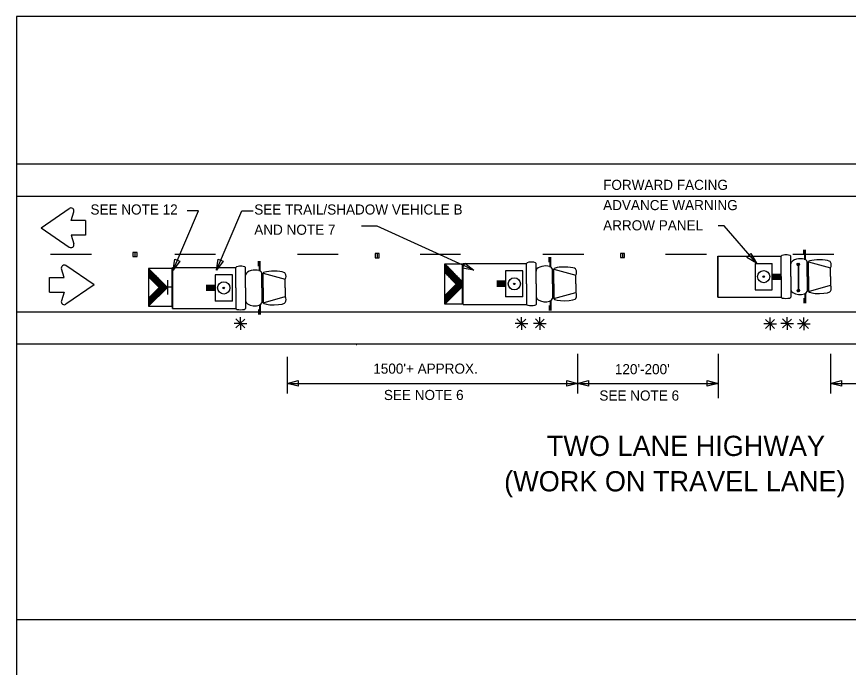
# Model space of a CAD drawing. Extents: x 1806907 to 1812607, y 675071 to 676228.
# Drawn here: x 1810956.7 to 1811449.9, y 675735.3 to 676121.2 of the extents above; entities that cross this region are included whole.
import ezdxf

# ---------------------------------------------------------------- set-up
doc = ezdxf.new("R2010")
doc.units = 0
for name, color, linetype in [('DSN_DRFT_Named-Boundary', 7, 'Continuous'), ('Level 1', 7, 'Continuous'), ('Working Level 1', 7, 'Continuous')]:
    doc.layers.add(name, color=color, linetype=linetype)

msp = doc.modelspace()

# ---------------------------------------------------------------- linework, layer by layer
at = {"layer": 'DSN_DRFT_Named-Boundary'}
msp.add_lwpolyline([(1810956.68, 675071.2), (1812606.68, 675071.2), (1812606.68, 676121.2), (1810956.68, 676121.2)], close=True, dxfattribs=at)
at = {"layer": 'Level 1'}
for points in [[(1811049.43, 675970.8), (1811064.48, 676006.06), (1811057.79, 676006.06)], [(1811075.16, 675970.8), (1811090.2, 676006.06), (1811096.89, 676006.06)], [(1811227.71, 675970.8), (1811170.45, 675996.86), (1811161.11, 675996.86)]]:
    msp.add_lwpolyline(points, dxfattribs=at)
at = {"layer": 'Working Level 1'}
for p, q in [((1810956.95, 676033.93), (1811756.7, 676033.93)), ((1810956.95, 676014.8), (1811756.7, 676014.8)), ((1810971.22, 675995.97), (1810987.89, 676007.41)), ((1810988.94, 676000.34), (1810990.57, 676005.41)), ((1810971.22, 675995.97), (1810987.89, 675984.54)), ((1810997.61, 676000.34), (1810988.94, 676000.34)), ((1810997.61, 676000.34), (1810997.61, 675991.61)), ((1810997.61, 675991.61), (1810988.94, 675991.61)), ((1810988.94, 675991.61), (1810990.57, 675986.53)), ((1811025.64, 675981.41), (1811025.63, 675978.98)), ((1811028.06, 675981.41), (1811025.64, 675981.41)), ((1811026.86, 675981.41), (1811026.85, 675978.98)), ((1811028.06, 675978.98), (1811028.06, 675981.41)), ((1811423.53, 675979.86), (1811423.53, 675982.83)), ((1811424, 675977), (1811424, 675982.83)), ((1811424.4, 675977), (1811424.4, 675982.83)), ((1811025.63, 675978.98), (1811028.06, 675978.98)), ((1811100.2, 675973.15), (1811100.2, 675976.12)), ((1811100.67, 675970.3), (1811100.67, 675976.12)), ((1811101.07, 675970.3), (1811101.07, 675976.12)), ((1811169.32, 675980.67), (1811169.31, 675978.24)), ((1811169.31, 675978.24), (1811171.74, 675978.24)), ((1811171.74, 675980.67), (1811169.32, 675980.67)), ((1811170.53, 675980.67), (1811170.53, 675978.24)), ((1811171.74, 675978.24), (1811171.74, 675980.67)), ((1811272.5, 675975.56), (1811272.5, 675978.53)), ((1811272.97, 675972.7), (1811272.97, 675978.53)), ((1811273.37, 675972.7), (1811273.37, 675978.53)), ((1811314.76, 675980.81), (1811314.75, 675978.38)), ((1811314.75, 675978.38), (1811317.18, 675978.38)), ((1811317.18, 675980.81), (1811314.76, 675980.81)), ((1811315.97, 675980.81), (1811315.97, 675978.38)), ((1811317.18, 675978.38), (1811317.18, 675980.81)), ((1811372.48, 675979.14), (1811372.48, 675954.88)), ((1811372.48, 675979.13), (1811410.02, 675979.13)), ((1811372.48, 675954.88), (1811372.48, 675979.13)), ((1811410.02, 675967.01), (1811410.02, 675979.13)), ((1811415.78, 675967.01), (1811415.78, 675979.13)), ((1810984.89, 675966.48), (1810983.26, 675971.55)), ((1811002.61, 675962.11), (1810985.94, 675973.55)), ((1811034.88, 675971.79), (1811046.07, 675960.62)), ((1811049.15, 675972.43), (1811086.69, 675972.43)), ((1811049.15, 675948.17), (1811049.15, 675972.43)), ((1811049.15, 675972.43), (1811049.15, 675948.18)), ((1811086.69, 675960.3), (1811086.69, 675972.43)), ((1811092.44, 675960.3), (1811092.44, 675972.43)), ((1811210.58, 675974.55), (1811220.94, 675964.2)), ((1811221.45, 675974.83), (1811258.99, 675974.83)), ((1811221.45, 675950.58), (1811221.45, 675974.83)), ((1811258.99, 675962.71), (1811258.99, 675974.83)), ((1811264.75, 675962.71), (1811264.75, 675974.83)), ((1811274.38, 675962.71), (1811274.38, 675971.44)), ((1811275.18, 675971.44), (1811288.31, 675967.85)), ((1811275.18, 675962.71), (1811275.18, 675971.44)), ((1811394.53, 675974.77), (1811404.79, 675974.77)), ((1811394.53, 675974.77), (1811394.53, 675959.25)), ((1811404.79, 675959.25), (1811404.79, 675974.77)), ((1811419.44, 675974.38), (1811419.44, 675974.38)), ((1811420.06, 675974.03), (1811420.06, 675958.98)), ((1811420.1, 675974.03), (1811420.1, 675958.98)), ((1811420.15, 675974.03), (1811420.15, 675958.98)), ((1811420.23, 675974.03), (1811420.23, 675958.98)), ((1811420.32, 675974.89), (1811420.32, 675974.89)), ((1811420.34, 675974.03), (1811420.34, 675958.98)), ((1811425.41, 675967.01), (1811425.41, 675975.74)), ((1811426.21, 675975.74), (1811439.34, 675972.15)), ((1811426.21, 675967.01), (1811426.21, 675975.74)), ((1811439.34, 675967.01), (1811439.34, 675972.15)), ((1810976.22, 675957.75), (1810976.22, 675966.48)), ((1810976.22, 675966.48), (1810984.89, 675966.48)), ((1811034.88, 675966.94), (1811041.29, 675960.55)), ((1811084.62, 675968.06), (1811074.36, 675968.06)), ((1811074.36, 675968.06), (1811074.36, 675952.54)), ((1811084.62, 675952.54), (1811084.62, 675968.06)), ((1811102.08, 675960.3), (1811102.08, 675969.04)), ((1811102.88, 675969.04), (1811116.01, 675965.45)), ((1811102.88, 675960.3), (1811102.88, 675969.04)), ((1811210.58, 675969.37), (1811217.41, 675962.57)), ((1811256.93, 675970.47), (1811246.66, 675970.47)), ((1811246.66, 675970.47), (1811246.66, 675954.94)), ((1811256.93, 675954.94), (1811256.93, 675970.47)), ((1811288.31, 675962.71), (1811288.31, 675967.85)), ((1811404.79, 675968.56), (1811410.02, 675968.56)), ((1811404.79, 675967.78), (1811410.02, 675967.78)), ((1811404.79, 675967.01), (1811410.02, 675967.01)), ((1811404.79, 675966.23), (1811410.02, 675966.23)), ((1811410.02, 675967.01), (1811410.02, 675954.88)), ((1811415.78, 675967.01), (1811415.78, 675954.88)), ((1811425.41, 675967.01), (1811425.41, 675958.27)), ((1811426.21, 675967.01), (1811426.21, 675958.27)), ((1811439.34, 675967.01), (1811439.34, 675961.86)), ((1811002.61, 675962.11), (1810985.94, 675950.68)), ((1811046.44, 675956.41), (1811046.44, 675964.82)), ((1811074.36, 675961.85), (1811069.13, 675961.85)), ((1811116.01, 675960.3), (1811116.01, 675965.45)), ((1811210.58, 675955.75), (1811217.41, 675962.57)), ((1811246.66, 675964.26), (1811241.44, 675964.26)), ((1811246.66, 675963.48), (1811241.44, 675963.48)), ((1811246.66, 675962.71), (1811241.44, 675962.71)), ((1811246.66, 675961.93), (1811241.44, 675961.93)), ((1811258.99, 675962.71), (1811258.99, 675950.58)), ((1811264.75, 675962.71), (1811264.75, 675950.58)), ((1811274.38, 675962.71), (1811274.38, 675953.97)), ((1811275.18, 675962.71), (1811275.18, 675953.97)), ((1811288.31, 675962.71), (1811288.31, 675957.56)), ((1811404.79, 675965.46), (1811410.02, 675965.46)), ((1811426.21, 675958.27), (1811439.34, 675961.86)), ((1810976.22, 675957.75), (1810984.89, 675957.75)), ((1810984.89, 675957.75), (1810983.26, 675952.68)), ((1811034.88, 675954.16), (1811041.29, 675960.55)), ((1811034.95, 675949.49), (1811046.07, 675960.62)), ((1811048.78, 675960.81), (1811046.37, 675960.81)), ((1811074.36, 675961.08), (1811069.13, 675961.08)), ((1811074.36, 675960.3), (1811069.13, 675960.3)), ((1811074.36, 675959.52), (1811069.13, 675959.52)), ((1811074.36, 675958.75), (1811069.13, 675958.75)), ((1811086.69, 675960.3), (1811086.69, 675948.18)), ((1811092.44, 675960.3), (1811092.44, 675948.18)), ((1811102.08, 675960.3), (1811102.08, 675951.57)), ((1811102.88, 675960.3), (1811102.88, 675951.57)), ((1811116.01, 675960.3), (1811116.01, 675955.15)), ((1811210.64, 675950.77), (1811220.89, 675961.02)), ((1811246.66, 675961.15), (1811241.44, 675961.15)), ((1811275.18, 675953.97), (1811288.31, 675957.56)), ((1811394.53, 675959.25), (1811404.79, 675959.25)), ((1811419.49, 675958.85), (1811419.49, 675958.85)), ((1811420.36, 675959.36), (1811420.36, 675959.36)), ((1811424, 675957.01), (1811424, 675951.19)), ((1811424.4, 675957.01), (1811424.4, 675951.19)), ((1811084.62, 675952.54), (1811074.36, 675952.54)), ((1811102.88, 675951.57), (1811116.01, 675955.15)), ((1811256.93, 675954.94), (1811246.66, 675954.94)), ((1811272.97, 675952.71), (1811272.97, 675946.88)), ((1811273.37, 675952.71), (1811273.37, 675946.88)), ((1811372.48, 675954.88), (1811410.02, 675954.88)), ((1811423.53, 675954.16), (1811423.53, 675951.19)), ((1811049.15, 675948.18), (1811086.69, 675948.18)), ((1811100.2, 675947.45), (1811100.2, 675944.48)), ((1811100.67, 675950.3), (1811100.67, 675944.48)), ((1811101.07, 675950.3), (1811101.07, 675944.48)), ((1811221.45, 675950.58), (1811258.99, 675950.58)), ((1811272.5, 675949.85), (1811272.5, 675946.88)), ((1810956.95, 675946.11), (1811756.7, 675946.11)), ((1811089.4, 675939.23), (1811086.74, 675941.89)), ((1811089.33, 675939.18), (1811092, 675941.84)), ((1811089.4, 675939.23), (1811089.4, 675943)), ((1811255.99, 675939.23), (1811253.33, 675941.89)), ((1811255.93, 675939.18), (1811258.59, 675941.84)), ((1811255.99, 675939.23), (1811255.99, 675943)), ((1811266.97, 675939.23), (1811264.31, 675941.89)), ((1811266.91, 675939.18), (1811269.57, 675941.84)), ((1811266.97, 675939.23), (1811266.97, 675943)), ((1811403.49, 675938.99), (1811400.83, 675941.65)), ((1811403.43, 675938.94), (1811406.09, 675941.6)), ((1811403.49, 675938.99), (1811403.49, 675942.76)), ((1811413.52, 675939.23), (1811410.86, 675941.89)), ((1811413.45, 675939.18), (1811416.12, 675941.84)), ((1811413.52, 675939.23), (1811413.52, 675943)), ((1811423.54, 675938.99), (1811420.88, 675941.65)), ((1811423.48, 675938.94), (1811426.14, 675941.6)), ((1811423.54, 675938.99), (1811423.54, 675942.76)), ((1811089.4, 675939.23), (1811085.63, 675939.23)), ((1811089.4, 675939.23), (1811086.74, 675936.57)), ((1811089.4, 675939.23), (1811092.06, 675936.57)), ((1811089.4, 675939.23), (1811089.4, 675935.47)), ((1811089.4, 675939.23), (1811093.16, 675939.23)), ((1811255.99, 675939.23), (1811252.23, 675939.23)), ((1811255.99, 675939.23), (1811253.33, 675936.57)), ((1811255.99, 675939.23), (1811258.65, 675936.57)), ((1811255.99, 675939.23), (1811255.99, 675935.47)), ((1811255.99, 675939.23), (1811259.75, 675939.23)), ((1811266.97, 675939.23), (1811263.21, 675939.23)), ((1811266.97, 675939.23), (1811264.31, 675936.57)), ((1811266.97, 675939.23), (1811269.63, 675936.57)), ((1811266.97, 675939.23), (1811266.97, 675935.47)), ((1811266.97, 675939.23), (1811270.73, 675939.23)), ((1811403.49, 675938.99), (1811399.73, 675938.99)), ((1811403.49, 675938.99), (1811400.83, 675936.33)), ((1811403.49, 675938.99), (1811406.15, 675936.33)), ((1811403.49, 675938.99), (1811403.49, 675935.23)), ((1811403.49, 675938.99), (1811407.25, 675938.99)), ((1811413.52, 675939.23), (1811409.75, 675939.23)), ((1811413.52, 675939.23), (1811410.86, 675936.57)), ((1811413.52, 675939.23), (1811416.18, 675936.57)), ((1811413.52, 675939.23), (1811413.52, 675935.47)), ((1811413.52, 675939.23), (1811417.28, 675939.23)), ((1811423.54, 675938.99), (1811419.78, 675938.99)), ((1811423.54, 675938.99), (1811420.88, 675936.33)), ((1811423.54, 675938.99), (1811426.2, 675936.33)), ((1811423.54, 675938.99), (1811423.54, 675935.23)), ((1811423.54, 675938.99), (1811427.3, 675938.99)), ((1810956.95, 675927.23), (1811756.7, 675927.23)), ((1811158.42, 675926.63), (1811157.94, 675926.63)), ((1811117.08, 675919.43), (1811117.08, 675897.64)), ((1811289.35, 675921.17), (1811289.35, 675897.64)), ((1811372.64, 675921.17), (1811372.64, 675894.99)), ((1811439.23, 675921.17), (1811439.23, 675897.64)), ((1811117.08, 675903.7), (1811289.35, 675903.7)), ((1811117.08, 675903.7), (1811122.85, 675903.7)), ((1811289.35, 675903.7), (1811288.19, 675903.7)), ((1811289.35, 675903.7), (1811293.89, 675903.7)), ((1811289.35, 675903.7), (1811372.64, 675903.7)), ((1811372.64, 675903.7), (1811368.13, 675903.7)), ((1811439.23, 675903.7), (1811443.77, 675903.7)), ((1811439.32, 675903.7), (1811522.61, 675903.7)), ((1810956.95, 675763.73), (1811757, 675763.73))]:
    msp.add_line(p, q, dxfattribs=at)
for points in [[(1811395.33, 675974.91), (1811376.24, 675997.09), (1811372.6, 675997.09)], [(1810976.79, 675980.35), (1811001.05, 675980.35)], [(1811050.43, 675980.35), (1811074.69, 675980.35)], [(1811123.19, 675980.35), (1811147.44, 675980.35)], [(1811195.94, 675980.35), (1811219.9, 675980.35)], [(1811268.7, 675980.35), (1811292.95, 675980.35)], [(1811341.45, 675980.35), (1811365.71, 675980.35)], [(1811416.95, 675980.35), (1811441.2, 675980.35)], [(1811034.88, 675971.26), (1811040.79, 675961.05)], [(1811035.38, 675971.3), (1811043.19, 675957.75)], [(1811210.58, 675974), (1811216.87, 675963.1)], [(1811210.58, 675973.06), (1811215.63, 675964.31)], [(1811210.58, 675972.12), (1811214.38, 675965.53)], [(1811210.58, 675971.18), (1811213.14, 675966.76)], [(1811211.11, 675974.03), (1811219.44, 675959.59)], [(1811212.39, 675972.74), (1811219.79, 675959.93)], [(1811213.67, 675971.47), (1811220.13, 675960.27)], [(1811419.42, 675974.12), (1811419.69, 675973.66)], [(1811419.44, 675974.38), (1811419.93, 675973.53)], [(1811419.5, 675974.56), (1811420.12, 675973.5)], [(1811419.59, 675974.7), (1811420.28, 675973.51)], [(1811419.7, 675974.8), (1811420.42, 675973.56)], [(1811419.82, 675974.88), (1811420.55, 675973.62)], [(1811419.97, 675974.92), (1811420.66, 675973.72)], [(1811420.12, 675974.96), (1811420.76, 675973.85)], [(1811420.3, 675974.93), (1811420.83, 675974.01)], [(1811420.51, 675974.85), (1811420.87, 675974.24)], [(1811034.88, 675970.39), (1811039.62, 675962.19)], [(1811034.88, 675969.51), (1811038.45, 675963.33)], [(1811034.88, 675968.63), (1811037.28, 675964.48)], [(1811034.88, 675967.75), (1811036.11, 675965.63)], [(1811034.88, 675966.87), (1811034.95, 675966.77)], [(1811036.58, 675970.09), (1811043.52, 675958.07)], [(1811037.77, 675968.9), (1811043.84, 675958.4)], [(1811038.98, 675967.7), (1811044.16, 675958.71)], [(1811040.17, 675966.5), (1811044.48, 675959.04)], [(1811210.58, 675970.24), (1811211.89, 675967.98)], [(1811210.58, 675969.31), (1811210.64, 675969.2)], [(1811214.95, 675970.19), (1811220.47, 675960.61)], [(1811216.22, 675968.91), (1811220.82, 675960.95)], [(1811217.5, 675967.63), (1811220.9, 675961.75)], [(1811218.78, 675966.36), (1811220.92, 675962.67)], [(1811041.37, 675965.3), (1811044.82, 675959.34)], [(1811042.57, 675964.1), (1811045.15, 675959.65)], [(1811043.77, 675962.91), (1811045.44, 675960.01)], [(1811044.88, 675961.82), (1811045.74, 675960.32)], [(1811216.23, 675961.4), (1811218.07, 675958.22)], [(1811216.58, 675961.74), (1811218.41, 675958.56)], [(1811216.92, 675962.08), (1811218.76, 675958.9)], [(1811217.26, 675962.42), (1811219.1, 675959.24)], [(1811220.06, 675965.09), (1811220.93, 675963.57)], [(1811037.29, 675956.56), (1811039.01, 675953.58)], [(1811037.61, 675956.88), (1811039.33, 675953.9)], [(1811037.93, 675957.2), (1811039.65, 675954.23)], [(1811038.25, 675957.53), (1811039.97, 675954.55)], [(1811038.57, 675957.84), (1811040.29, 675954.87)], [(1811038.9, 675958.17), (1811040.62, 675955.18)], [(1811039.22, 675958.49), (1811040.94, 675955.51)], [(1811039.54, 675958.8), (1811041.26, 675955.83)], [(1811039.86, 675959.13), (1811041.59, 675956.15)], [(1811040.18, 675959.45), (1811041.91, 675956.47)], [(1811040.51, 675959.77), (1811042.23, 675956.79)], [(1811040.82, 675960.1), (1811042.56, 675957.11)], [(1811041.15, 675960.42), (1811042.88, 675957.43)], [(1811211.42, 675956.59), (1811213.25, 675953.43)], [(1811211.77, 675956.94), (1811213.6, 675953.77)], [(1811212.11, 675957.28), (1811213.94, 675954.12)], [(1811212.46, 675957.62), (1811214.29, 675954.45)], [(1811212.8, 675957.96), (1811214.63, 675954.8)], [(1811213.15, 675958.31), (1811214.97, 675955.14)], [(1811213.49, 675958.65), (1811215.32, 675955.48)], [(1811213.83, 675959), (1811215.66, 675955.82)], [(1811214.17, 675959.34), (1811216.01, 675956.16)], [(1811214.51, 675959.68), (1811216.35, 675956.51)], [(1811214.86, 675960.02), (1811216.7, 675956.85)], [(1811215.2, 675960.37), (1811217.04, 675957.19)], [(1811215.55, 675960.71), (1811217.38, 675957.53)], [(1811215.89, 675961.05), (1811217.72, 675957.87)], [(1811419.47, 675958.59), (1811419.73, 675958.13)], [(1811419.49, 675958.85), (1811419.97, 675958)], [(1811419.55, 675959.03), (1811420.16, 675957.97)], [(1811419.64, 675959.17), (1811420.32, 675957.98)], [(1811419.74, 675959.27), (1811420.46, 675958.03)], [(1811419.86, 675959.35), (1811420.59, 675958.09)], [(1811420.01, 675959.39), (1811420.7, 675958.19)], [(1811420.16, 675959.42), (1811420.8, 675958.32)], [(1811420.34, 675959.4), (1811420.87, 675958.48)], [(1811420.56, 675959.32), (1811420.91, 675958.71)], [(1811034.88, 675953.68), (1811036.43, 675951.02)], [(1811034.88, 675952.8), (1811036.1, 675950.7)], [(1811034.88, 675951.92), (1811035.78, 675950.38)], [(1811035.03, 675954.31), (1811036.75, 675951.35)], [(1811035.36, 675954.63), (1811037.07, 675951.66)], [(1811035.68, 675954.95), (1811037.39, 675951.98)], [(1811036, 675955.28), (1811037.72, 675952.3)], [(1811036.32, 675955.59), (1811038.04, 675952.63)], [(1811036.64, 675955.91), (1811038.36, 675952.94)], [(1811036.96, 675956.23), (1811038.68, 675953.26)], [(1811210.58, 675955.25), (1811212.23, 675952.4)], [(1811210.58, 675954.31), (1811211.88, 675952.06)], [(1811210.58, 675953.36), (1811211.54, 675951.72)], [(1811210.58, 675952.43), (1811211.19, 675951.37)], [(1811210.58, 675951.49), (1811210.85, 675951.04)], [(1811210.74, 675955.91), (1811212.56, 675952.75)], [(1811211.09, 675956.25), (1811212.91, 675953.08)], [(1811034.88, 675951.04), (1811035.46, 675950.06)], [(1811034.88, 675950.16), (1811035.13, 675949.74)]]:
    msp.add_lwpolyline(points, dxfattribs=at)
for points in [[(1811053.48, 675976.14), (1811049.43, 675970.8), (1811050.49, 675977.42)], [(1811079.2, 675976.14), (1811075.16, 675970.8), (1811076.21, 675977.42)], [(1811391.95, 675980.69), (1811395.33, 675974.91), (1811389.63, 675978.42)], [(1811034.88, 675971.79), (1811034.88, 675949.48), (1811048.82, 675949.48), (1811048.82, 675971.79)], [(1811220.97, 675950.77), (1811210.58, 675950.77), (1811210.58, 675974.55), (1811220.97, 675974.55)], [(1811222.46, 675974.97), (1811227.71, 675970.8), (1811221.12, 675972.01)], [(1811123.58, 675902.08), (1811117.08, 675903.7), (1811123.58, 675905.33)], [(1811282.85, 675905.33), (1811289.35, 675903.7), (1811282.85, 675902.08)], [(1811295.85, 675902.08), (1811289.35, 675903.7), (1811295.85, 675905.33)], [(1811366.14, 675905.33), (1811372.64, 675903.7), (1811366.14, 675902.08)], [(1811445.73, 675902.08), (1811439.23, 675903.7), (1811445.73, 675905.33)]]:
    msp.add_lwpolyline(points, close=True, dxfattribs=at)
for centre, radius in [((1811420.14, 675974.23), 0.728), ((1811251.8, 675962.71), 3.62), ((1811399.66, 675967.01), 3.62), ((1811399.66, 675967.01), 0.451), ((1811079.49, 675960.3), 3.62), ((1811251.8, 675962.71), 0.451), ((1811079.49, 675960.3), 0.451), ((1811420.18, 675958.69), 0.728)]:
    msp.add_circle(centre, radius, dxfattribs=at)
for centre, radius, start, end in [((1810988.88, 676005.95), 1.77, 342.1824, 124.4455), ((1810988.88, 675985.99), 1.77, 235.5545, 17.8176), ((1810984.95, 675972.09), 1.77, 55.5545, 197.8176), ((1811285.1, 675969.57), 3.64, 331.8801, 28.1199), ((1811436.13, 675973.87), 3.64, 331.8801, 28.1199), ((1811112.8, 675967.16), 3.64, 331.8801, 28.1199), ((1811436.13, 675960.14), 3.64, 331.8801, 28.1199), ((1811285.1, 675955.84), 3.64, 331.8801, 28.1199), ((1810984.95, 675952.14), 1.77, 162.1824, 304.4455), ((1811112.8, 675953.44), 3.64, 331.8801, 28.1199)]:
    msp.add_arc(centre, radius, start, end, dxfattribs=at)
for centre, major_axis, ratio, start_param, end_param in [((1811412.9, 675979.13), (2.88, 0), 0.269913, 0, 3.141593), ((1811420.59, 675975.15), (4.82, 0.6), 0.503092, 0, 3.141593), ((1811432.78, 675975.67), (6.56, -0.08), 0.2034, 0, 3.141593), ((1811089.57, 675972.42), (2.88, 0), 0.269913, 0, 3.141593), ((1811097.26, 675968.44), (4.82, 0.6), 0.503092, 0, 3.141593), ((1811261.87, 675974.83), (2.88, 0), 0.269913, 0, 3.141593), ((1811269.56, 675970.85), (4.82, 0.6), 0.503092, 0, 3.141593), ((1811281.75, 675971.37), (6.56, -0.08), 0.2034, 0, 3.141593), ((1811109.44, 675968.96), (6.56, -0.08), 0.2034, 0, 3.141593), ((1811420.59, 675958.87), (4.82, -0.6), 0.503092, 3.141593, 6.283185), ((1811432.78, 675958.35), (6.56, 0.08), 0.2034, 3.141593, 6.283185), ((1811097.26, 675952.16), (4.82, -0.6), 0.503092, 3.141593, 6.283185), ((1811109.44, 675951.64), (6.56, 0.08), 0.2034, 3.141593, 6.283185), ((1811269.56, 675954.57), (4.82, -0.6), 0.503092, 3.141593, 6.283185), ((1811281.75, 675954.05), (6.56, 0.08), 0.2034, 3.141593, 6.283185), ((1811412.9, 675954.88), (2.88, 0), 0.269913, 3.141593, 6.283185), ((1811089.57, 675948.17), (2.88, 0), 0.269913, 3.141593, 6.283185), ((1811261.87, 675950.58), (2.88, 0), 0.269913, 3.141593, 6.283185)]:
    msp.add_ellipse(centre, major_axis=major_axis, ratio=ratio, start_param=start_param, end_param=end_param, dxfattribs=at)

# ---------------------------------------------------------------- texts
for s, height, p in [('FORWARD FACING', 6, (1811304.47, 676018.44)), ('ADVANCE WARNING ', 6, (1811304.47, 676006.44)), ('SEE NOTE 12 ', 6, (1811000.46, 676003.83)), ('SEE TRAIL/SHADOW VEHICLE B', 6, (1811097.59, 676003.83)), ('AND NOTE 7 ', 6, (1811097.59, 675991.83)), ('ARROW PANEL', 6, (1811304.47, 675994.44)), ("1500'+ APPROX.", 6, (1811168.16, 675909.45)), ("120'-200'", 6, (1811311.43, 675909.13)), ('SEE NOTE 6', 6, (1811174.47, 675893.83)), ('SEE NOTE 6', 6, (1811302.25, 675893.51)), ('TWO LANE HIGHWAY', 12, (1811271.1, 675860.65)), ('(WORK ON TRAVEL LANE)', 12, (1811245.78, 675839.65))]:
    msp.add_text(s, height=height, dxfattribs=at).set_placement(p)

doc.saveas('drawing.dxf')
